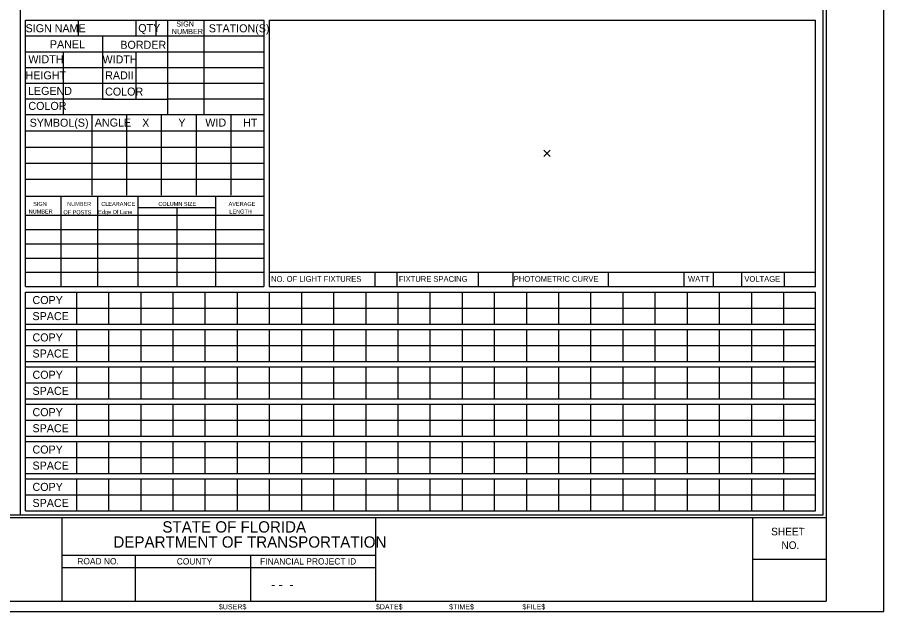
# Model space of a CAD drawing. Extents: x 1274.1 to 1363.1, y 833.5 to 890.6.
# Drawn here: x 1318.48 to 1363.1, y 833.48 to 864.07 of the extents above; entities that cross this region are included whole.
import ezdxf

# ---------------------------------------------------------------- set-up
doc = ezdxf.new("R2010")
doc.units = 0
for name, color, linetype in [('NonPlottingEle_dp', 7, 'Continuous'), ('PlotBorder_dp', 7, 'Continuous'), ('SheetBorder_dp', 7, 'Continuous'), ('SheetLines_dp', 7, 'Continuous'), ('SheetLinesMisc2_dp', 7, 'Continuous'), ('TextMinor', 7, 'Continuous'), ('TextMisc', 7, 'Continuous')]:
    doc.layers.add(name, color=color, linetype=linetype)

msp = doc.modelspace()

# ---------------------------------------------------------------- linework, layer by layer
at = {"layer": 'NonPlottingEle_dp'}
for p, q in [((1345.595, 857.226), (1345.916, 856.905)), ((1345.595, 856.905), (1345.916, 857.226))]:
    msp.add_line(p, q, dxfattribs=at)
at = {"layer": 'PlotBorder_dp'}
msp.add_lwpolyline([(1274.135, 833.481), (1363.097, 833.481), (1363.097, 890.634), (1274.135, 890.634)], close=True, dxfattribs=at)
at = {"layer": 'SheetBorder_dp'}
for p, q in [((1360.132, 890.095), (1360.132, 834.02)), ((1277.101, 838.334), (1360.132, 838.334)), ((1277.101, 834.02), (1360.132, 834.02))]:
    msp.add_line(p, q, dxfattribs=at)
at = {"layer": 'SheetLines_dp'}
for p, q in [((1320.773, 838.334), (1320.773, 834.02)), ((1336.948, 834.02), (1336.948, 838.334)), ((1356.358, 834.02), (1356.358, 838.334)), ((1320.773, 836.393), (1336.948, 836.393)), ((1324.547, 836.393), (1324.547, 834.02)), ((1330.478, 836.393), (1330.478, 834.02)), ((1320.773, 835.746), (1336.948, 835.746)), ((1356.358, 836.177), (1360.132, 836.177))]:
    msp.add_line(p, q, dxfattribs=at)
at = {"layer": 'SheetLinesMisc2_dp'}
for p, q in [((1318.617, 889.967), (1318.617, 838.462)), ((1359.988, 838.462), (1359.988, 889.967)), ((1318.901, 850.212), (1318.901, 863.919)), ((1318.901, 863.919), (1331.169, 863.919)), ((1321.605, 863.919), (1321.605, 863.109)), ((1324.588, 863.919), (1324.588, 863.109)), ((1325.606, 863.919), (1325.606, 863.109)), ((1326.213, 863.919), (1326.213, 859.061)), ((1328.08, 863.919), (1328.08, 859.061)), ((1331.169, 863.919), (1331.169, 850.212)), ((1331.451, 863.919), (1359.592, 863.919)), ((1331.451, 863.919), (1331.451, 850.231)), ((1359.592, 850.231), (1359.592, 863.92)), ((1318.901, 863.109), (1331.169, 863.109)), ((1322.866, 863.109), (1322.866, 859.862)), ((1318.901, 862.3), (1331.169, 862.3)), ((1320.84, 862.3), (1320.84, 859.061)), ((1324.577, 862.291), (1324.577, 859.862)), ((1318.901, 861.49), (1331.169, 861.49)), ((1318.901, 860.68), (1331.169, 860.68)), ((1318.901, 859.871), (1323.451, 859.871)), ((1322.866, 859.862), (1326.213, 859.862)), ((1326.213, 859.871), (1331.169, 859.871)), ((1318.901, 859.061), (1331.169, 859.061)), ((1322.308, 859.045), (1322.308, 854.911)), ((1324.101, 859.045), (1324.101, 854.911)), ((1325.893, 859.045), (1325.893, 854.911)), ((1327.686, 859.045), (1327.686, 854.911)), ((1329.479, 859.045), (1329.479, 854.911)), ((1318.904, 858.218), (1331.169, 858.218)), ((1318.904, 857.391), (1331.169, 857.391)), ((1318.904, 856.565), (1331.169, 856.565)), ((1318.904, 855.738), (1331.169, 855.738)), ((1318.901, 854.872), (1331.169, 854.872)), ((1320.722, 854.872), (1320.722, 850.212)), ((1322.603, 854.872), (1322.603, 850.212)), ((1324.681, 854.872), (1324.681, 850.212)), ((1328.682, 854.872), (1328.682, 850.212)), ((1324.681, 854.279), (1328.679, 854.279)), ((1326.69, 854.279), (1326.69, 850.212)), ((1318.901, 853.884), (1331.169, 853.884)), ((1318.901, 853.149), (1331.169, 853.149)), ((1318.901, 852.415), (1331.169, 852.415)), ((1318.901, 851.68), (1331.169, 851.68)), ((1318.901, 850.946), (1331.169, 850.946)), ((1331.451, 850.946), (1359.592, 850.946)), ((1336.887, 850.946), (1336.887, 850.212)), ((1338.026, 850.946), (1338.026, 850.212)), ((1342.216, 850.946), (1342.216, 850.212)), ((1344, 850.946), (1344, 850.212)), ((1348.899, 850.946), (1348.899, 850.212)), ((1352.81, 850.946), (1352.81, 850.212)), ((1354.319, 850.946), (1354.319, 850.212)), ((1355.775, 850.946), (1355.775, 850.212)), ((1357.967, 850.946), (1357.967, 850.212)), ((1318.901, 850.212), (1331.169, 850.212)), ((1331.451, 850.231), (1331.451, 850.213)), ((1331.451, 850.212), (1359.592, 850.212)), ((1359.592, 850.213), (1359.592, 850.231)), ((1318.9, 849.93), (1359.592, 849.93)), ((1318.9, 838.662), (1318.9, 849.93)), ((1321.52, 849.93), (1321.52, 848.276)), ((1323.175, 849.93), (1323.175, 848.276)), ((1324.83, 849.93), (1324.83, 848.276)), ((1326.485, 849.93), (1326.485, 848.276)), ((1328.141, 849.93), (1328.141, 848.276)), ((1329.796, 849.93), (1329.796, 848.276)), ((1331.451, 849.93), (1331.451, 848.276)), ((1333.107, 849.93), (1333.107, 848.276)), ((1334.762, 849.93), (1334.762, 848.276)), ((1336.418, 849.93), (1336.418, 848.276)), ((1338.073, 849.93), (1338.073, 848.276)), ((1339.728, 849.93), (1339.728, 848.276)), ((1341.384, 849.93), (1341.384, 848.276)), ((1343.039, 849.93), (1343.039, 848.276)), ((1344.694, 849.93), (1344.694, 848.276)), ((1346.349, 849.93), (1346.349, 848.276)), ((1348.005, 849.93), (1348.005, 848.276)), ((1349.66, 849.93), (1349.66, 848.276)), ((1351.315, 849.93), (1351.315, 848.276)), ((1352.971, 849.93), (1352.971, 848.276)), ((1354.626, 849.93), (1354.626, 848.276)), ((1356.282, 849.93), (1356.282, 848.276)), ((1357.937, 849.93), (1357.937, 848.276)), ((1359.592, 838.662), (1359.592, 849.93)), ((1318.9, 849.103), (1359.592, 849.103)), ((1318.9, 848.276), (1359.592, 848.276)), ((1318.9, 848.007), (1359.592, 848.007)), ((1321.52, 848.007), (1321.52, 846.353)), ((1323.175, 848.007), (1323.175, 846.353)), ((1324.83, 848.007), (1324.83, 846.353)), ((1326.485, 848.007), (1326.485, 846.353)), ((1328.141, 848.007), (1328.141, 846.353)), ((1329.796, 848.007), (1329.796, 846.353)), ((1331.451, 848.007), (1331.451, 846.353)), ((1333.107, 848.007), (1333.107, 846.353)), ((1334.762, 848.007), (1334.762, 846.353)), ((1336.418, 848.007), (1336.418, 846.353)), ((1338.073, 848.007), (1338.073, 846.353)), ((1339.728, 848.007), (1339.728, 846.353)), ((1341.384, 848.007), (1341.384, 846.353)), ((1343.039, 848.007), (1343.039, 846.353)), ((1344.694, 848.007), (1344.694, 846.353)), ((1346.349, 848.007), (1346.349, 846.353)), ((1348.005, 848.007), (1348.005, 846.353)), ((1349.66, 848.007), (1349.66, 846.353)), ((1351.315, 848.007), (1351.315, 846.353)), ((1352.971, 848.007), (1352.971, 846.353)), ((1354.626, 848.007), (1354.626, 846.353)), ((1356.282, 848.007), (1356.282, 846.353)), ((1357.937, 848.007), (1357.937, 846.353)), ((1318.9, 847.18), (1359.592, 847.18)), ((1318.9, 846.353), (1359.592, 846.353)), ((1318.9, 846.084), (1359.592, 846.084)), ((1321.52, 846.084), (1321.52, 844.431)), ((1323.175, 846.084), (1323.175, 844.431)), ((1324.83, 846.084), (1324.83, 844.431)), ((1326.485, 846.084), (1326.485, 844.431)), ((1328.141, 846.084), (1328.141, 844.431)), ((1329.796, 846.084), (1329.796, 844.431)), ((1331.451, 846.084), (1331.451, 844.431)), ((1333.107, 846.084), (1333.107, 844.431)), ((1334.762, 846.084), (1334.762, 844.431)), ((1336.418, 846.084), (1336.418, 844.431)), ((1338.073, 846.084), (1338.073, 844.431)), ((1339.728, 846.084), (1339.728, 844.431)), ((1341.384, 846.084), (1341.384, 844.431)), ((1343.039, 846.084), (1343.039, 844.431)), ((1344.694, 846.084), (1344.694, 844.431)), ((1346.349, 846.084), (1346.349, 844.431)), ((1348.005, 846.084), (1348.005, 844.431)), ((1349.66, 846.084), (1349.66, 844.431)), ((1351.315, 846.084), (1351.315, 844.431)), ((1352.971, 846.084), (1352.971, 844.431)), ((1354.626, 846.084), (1354.626, 844.431)), ((1356.282, 846.084), (1356.282, 844.431)), ((1357.937, 846.084), (1357.937, 844.431)), ((1318.9, 845.257), (1359.592, 845.257)), ((1318.9, 844.431), (1359.592, 844.431)), ((1318.9, 844.161), (1359.592, 844.161)), ((1321.52, 844.161), (1321.52, 842.508)), ((1323.175, 844.161), (1323.175, 842.508)), ((1324.83, 844.161), (1324.83, 842.508)), ((1326.485, 844.161), (1326.485, 842.508)), ((1328.141, 844.161), (1328.141, 842.508)), ((1329.796, 844.161), (1329.796, 842.508)), ((1331.451, 844.161), (1331.451, 842.508)), ((1333.107, 844.161), (1333.107, 842.508)), ((1334.762, 844.161), (1334.762, 842.508)), ((1336.418, 844.161), (1336.418, 842.508)), ((1338.073, 844.161), (1338.073, 842.508)), ((1339.728, 844.161), (1339.728, 842.508)), ((1341.384, 844.161), (1341.384, 842.508)), ((1343.039, 844.161), (1343.039, 842.508)), ((1344.694, 844.161), (1344.694, 842.508)), ((1346.349, 844.161), (1346.349, 842.508)), ((1348.005, 844.161), (1348.005, 842.508)), ((1349.66, 844.161), (1349.66, 842.508)), ((1351.315, 844.161), (1351.315, 842.508)), ((1352.971, 844.161), (1352.971, 842.508)), ((1354.626, 844.161), (1354.626, 842.508)), ((1356.282, 844.161), (1356.282, 842.508)), ((1357.937, 844.161), (1357.937, 842.508)), ((1318.9, 843.335), (1359.592, 843.335)), ((1318.9, 842.508), (1359.592, 842.508)), ((1318.9, 842.238), (1359.592, 842.238)), ((1321.52, 842.238), (1321.52, 840.585)), ((1323.175, 842.238), (1323.175, 840.585)), ((1324.83, 842.238), (1324.83, 840.585)), ((1326.485, 842.238), (1326.485, 840.585)), ((1328.141, 842.238), (1328.141, 840.585)), ((1329.796, 842.238), (1329.796, 840.585)), ((1331.451, 842.238), (1331.451, 840.585)), ((1333.107, 842.238), (1333.107, 840.585)), ((1334.762, 842.238), (1334.762, 840.585)), ((1336.418, 842.238), (1336.418, 840.585)), ((1338.073, 842.238), (1338.073, 840.585)), ((1339.728, 842.238), (1339.728, 840.585)), ((1341.384, 842.238), (1341.384, 840.585)), ((1343.039, 842.238), (1343.039, 840.585)), ((1344.694, 842.238), (1344.694, 840.585)), ((1346.349, 842.238), (1346.349, 840.585)), ((1348.005, 842.238), (1348.005, 840.585)), ((1349.66, 842.238), (1349.66, 840.585)), ((1351.315, 842.238), (1351.315, 840.585)), ((1352.971, 842.238), (1352.971, 840.585)), ((1354.626, 842.238), (1354.626, 840.585)), ((1356.282, 842.238), (1356.282, 840.585)), ((1357.937, 842.238), (1357.937, 840.585)), ((1318.9, 841.411), (1359.592, 841.411)), ((1318.9, 840.585), (1359.592, 840.585)), ((1318.9, 840.315), (1359.592, 840.315)), ((1321.52, 840.315), (1321.52, 838.662)), ((1323.175, 840.315), (1323.175, 838.662)), ((1324.83, 840.315), (1324.83, 838.662)), ((1326.485, 840.315), (1326.485, 838.662)), ((1328.141, 840.315), (1328.141, 838.662)), ((1329.796, 840.315), (1329.796, 838.662)), ((1331.451, 840.315), (1331.451, 838.662)), ((1333.107, 840.315), (1333.107, 838.662)), ((1334.762, 840.315), (1334.762, 838.662)), ((1336.418, 840.315), (1336.418, 838.662)), ((1338.073, 840.315), (1338.073, 838.662)), ((1339.728, 840.315), (1339.728, 838.662)), ((1341.384, 840.315), (1341.384, 838.662)), ((1343.039, 840.315), (1343.039, 838.662)), ((1344.694, 840.315), (1344.694, 838.662)), ((1346.349, 840.315), (1346.349, 838.662)), ((1348.005, 840.315), (1348.005, 838.662)), ((1349.66, 840.315), (1349.66, 838.662)), ((1351.315, 840.315), (1351.315, 838.662)), ((1352.971, 840.315), (1352.971, 838.662)), ((1354.626, 840.315), (1354.626, 838.662)), ((1356.282, 840.315), (1356.282, 838.662)), ((1357.937, 840.315), (1357.937, 838.662)), ((1318.9, 839.489), (1359.592, 839.489)), ((1277.247, 838.462), (1359.988, 838.462)), ((1318.9, 838.662), (1359.592, 838.662))]:
    msp.add_line(p, q, dxfattribs=at)

# ---------------------------------------------------------------- texts
at = {"layer": 'TextMinor'}
for s, height, p in [('SIGN', 0.2696, (1326.664, 863.594)), ('SIGN NAME', 0.4125, (1318.901, 863.299)), ('QTY', 0.4125, (1324.705, 863.313)), ('NUMBER', 0.2696, (1326.429, 863.202)), ('STATION(S)', 0.4125, (1328.338, 863.297)), ('PANEL', 0.4125, (1320.155, 862.476)), ('BORDER', 0.4125, (1323.783, 862.448)), ('WIDTH', 0.4125, (1319.047, 861.706)), ('WIDTH', 0.4125, (1322.866, 861.697)), ('HEIGHT', 0.4125, (1318.901, 860.876)), ('RADII', 0.4125, (1323.001, 860.877)), ('LEGEND', 0.4125, (1319.025, 860.075)), ('COLOR', 0.4125, (1322.998, 860.04)), ('COLOR', 0.4125, (1319.047, 859.302)), ('SYMBOL(S)', 0.4125, (1319.112, 858.437)), ('ANGLE', 0.4125, (1322.466, 858.446)), ('X', 0.412, (1324.907, 858.437)), ('Y', 0.412, (1326.771, 858.437)), ('WID', 0.4125, (1328.159, 858.446)), ('HT', 0.4125, (1330.103, 858.438)), ('SIGN', 0.2062, (1319.294, 854.363)), ('NUMBER', 0.2062, (1321.045, 854.36)), ('CLEARANCE', 0.2062, (1322.801, 854.362)), ('COLUMN SIZE', 0.20623, (1325.74, 854.362)), ('AVERAGE', 0.2062, (1329.358, 854.362)), ('NUMBER', 0.2062, (1319.063, 853.971)), ('OF POSTS', 0.2062, (1320.85, 853.932)), ('Edge Of Lane', 0.20623, (1322.642, 853.947)), ('LENGTH', 0.2062, (1329.397, 853.971)), ('NO. OF LIGHT FIXTURES', 0.2923, (1331.546, 850.458)), ('FIXTURE SPACING', 0.2923, (1338.127, 850.458)), ('PHOTOMETRIC CURVE', 0.2923, (1344.046, 850.458)), ('WATT', 0.2923, (1353.019, 850.458)), ('VOLTAGE', 0.2923, (1355.921, 850.458)), ('COPY', 0.4125, (1319.258, 849.311)), ('SPACE', 0.4125, (1319.258, 848.485)), ('COPY', 0.4125, (1319.258, 847.388)), ('SPACE', 0.4125, (1319.258, 846.561)), ('COPY', 0.4125, (1319.258, 845.466)), ('SPACE', 0.4125, (1319.258, 844.639)), ('COPY', 0.4125, (1319.258, 843.542)), ('SPACE', 0.4125, (1319.258, 842.716)), ('COPY', 0.4125, (1319.258, 841.619)), ('SPACE', 0.4125, (1319.258, 840.793)), ('COPY', 0.4125, (1319.258, 839.697)), ('SPACE', 0.4125, (1319.258, 838.87)), ('$USER$', 0.2642, (1328.855, 833.6)), ('$DATE$', 0.2642, (1336.942, 833.6)), ('$TIME$', 0.2642, (1340.716, 833.6)), ('$FILE$', 0.2642, (1344.491, 833.6))]:
    msp.add_text(s, height=height, dxfattribs=at).set_placement(p)
at = {"layer": 'TextMisc'}
for s, height, p in [('STATE OF FLORIDA', 0.58231, (1325.949, 837.552)), ('DEPARTMENT OF TRANSPORTATION', 0.58231, (1323.426, 836.775)), ('ROAD NO.', 0.3235, (1321.566, 835.913)), ('COUNTY', 0.3235, (1326.688, 835.907)), ('FINANCIAL PROJECT ID', 0.3235, (1330.98, 835.907)), ('      - -  -  ', 0.47448, (1330.489, 834.651))]:
    msp.add_text(s, height=height, dxfattribs=at).set_placement(p)
for s, p in [('SHEET', (1357.302, 837.411)), ('NO.', (1357.83, 836.711))]:
    msp.add_text(s, height=0.3882, rotation=359.8607, dxfattribs=at).set_placement(p)

doc.saveas('drawing.dxf')
